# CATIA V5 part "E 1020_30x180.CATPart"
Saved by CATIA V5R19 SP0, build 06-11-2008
Nomenclature: E 1020_30x180
Description: PART-E 1020_30x180-DESC
Property "Hersteller": "Meusburger"
Property "Material": "1.7131 ~ 60HRC"
Property "Bestellnummer": "E 1020/30x180"
Property "Teilenummer": "E 1020/30x180"
Property "Beschreibung": "Führungsbolzen mit zwei Passdurchm. und Schmiernuten _ Guide bolt with two fitting diameters and oil grooves"
Material "Steel": density 7860 kg/m3, Young's modulus 2e+11 Pa, Poisson ratio 0.266, thermal expansion 1.17e-05 1/K
Bounding box of the stored display mesh (mm): x -17.3 to 17.3, y -17.29 to 17.29, z 0 to 180
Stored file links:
  G:\UTB\Kombinované\Bakalářská práce\Catia\FORMA\E 1020_30x180.CATPart
  D:\Aplikace\CATIA\Nová složka\win_b64\startup\materials\Catalog.CATMaterial
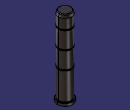
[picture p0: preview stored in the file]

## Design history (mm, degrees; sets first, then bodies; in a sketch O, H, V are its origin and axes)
Body1 "E 1020_30x180" (main body)
  Solid1: solid without history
